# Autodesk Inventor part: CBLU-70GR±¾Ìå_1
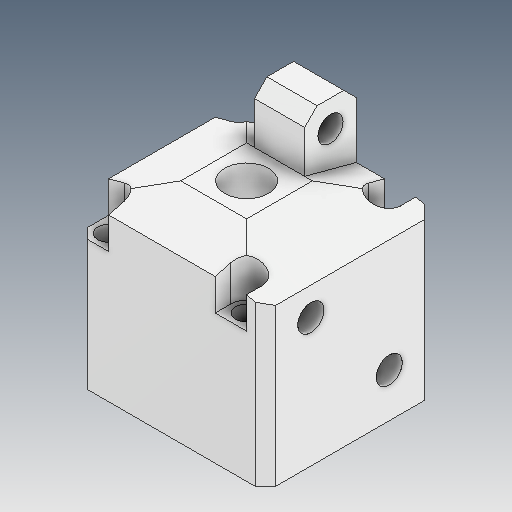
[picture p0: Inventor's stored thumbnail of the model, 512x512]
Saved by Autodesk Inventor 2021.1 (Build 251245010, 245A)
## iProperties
Created: 2021-05
Part Number: CBLU-70GR±¾Ìå_1
Material: Ogólny
Document SubType Name: Modeling
Designer: user
Density: 1 g/cm^3
Appearance: Domyślna
Author: user
Revision Number: ÈÎºÎ
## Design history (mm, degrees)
feature "ÊäÈë1"
feature "ÊäÈë2"
node "Bryła1"
node "Bryła2"
